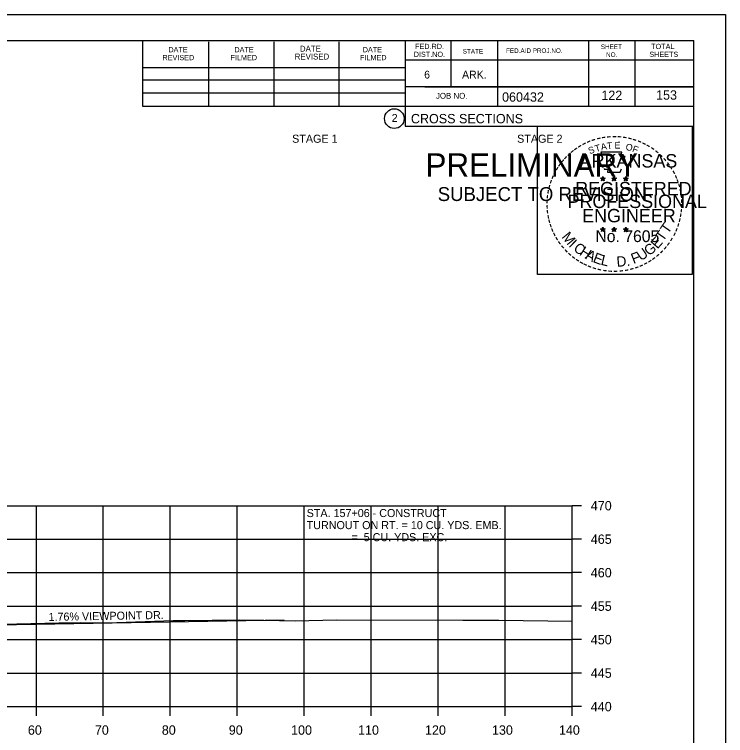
# Model space of a CAD drawing. Extents: x 1538688 to 1540766, y 656250 to 671912.
# Drawn here: x 1538914.9 to 1539021.1, y 666470.4 to 666578.1 of the extents above; entities that cross this region are included whole.
import ezdxf

# ---------------------------------------------------------------- set-up
doc = ezdxf.new("R2010")
doc.units = 0
for name, color, linetype in [('16', 7, 'Continuous'), ('18', 7, 'Continuous'), ('22', 7, 'Continuous'), ('26', 7, 'Continuous'), ('37', 7, 'Continuous'), ('7', 7, 'Continuous'), ('8', 7, 'Continuous'), ('9', 7, 'Continuous'), ('Borings', 7, 'Continuous'), ('Default', 7, 'Continuous'), ('Horizontal Alignment', 7, 'Continuous'), ('RipRap', 7, 'Continuous')]:
    doc.layers.add(name, color=color, linetype=linetype)

msp = doc.modelspace()

# ---------------------------------------------------------------- linework, layer by layer
at = {"layer": '18'}
msp.add_lwpolyline([(1538911.06, 666487.02), (1538921.53, 666487.26), (1538923.34, 666487.3), (1538924.76, 666487.31), (1538928.83, 666487.28), (1538938.6, 666487.62), (1538939.6, 666487.65), (1538940.37, 666487.65), (1538948.49, 666487.74), (1538951.25, 666487.66), (1538952.15, 666487.66), (1538956.85, 666487.6), (1538963.01, 666487.74), (1538981.87, 666487.66), (1538986.32, 666487.67), (1538987.26, 666487.66), (1538998.18, 666487.53)], dxfattribs=at)
at = {"layer": '22'}
for p, q in [((1538718.18, 666504.77), (1538998.18, 666504.77)), ((1538918.18, 666474.77), (1538918.18, 666504.77)), ((1538928.18, 666474.77), (1538928.18, 666504.77)), ((1538938.18, 666474.77), (1538938.18, 666504.77)), ((1538948.18, 666474.77), (1538948.18, 666504.77)), ((1538958.18, 666474.77), (1538958.18, 666504.77)), ((1538968.18, 666474.77), (1538968.18, 666504.77)), ((1538978.18, 666474.77), (1538978.18, 666504.77)), ((1538988.18, 666474.77), (1538988.18, 666504.77)), ((1538998.18, 666474.77), (1538998.18, 666504.77)), ((1538718.18, 666499.77), (1538998.18, 666499.77)), ((1538718.18, 666494.77), (1538998.18, 666494.77)), ((1538718.18, 666489.77), (1538998.18, 666489.77)), ((1538718.18, 666484.77), (1538998.18, 666484.77)), ((1538718.18, 666479.77), (1538998.18, 666479.77)), ((1538718.18, 666474.77), (1538998.18, 666474.77))]:
    msp.add_line(p, q, dxfattribs=at)
at = {"layer": '26'}
msp.add_line((1538687.78, 666578.12), (1539021.11, 666578.12), dxfattribs=at)
for points in [[(1538687.77, 666578.12), (1539021.11, 666578.12), (1539021.11, 666364.78), (1538687.77, 666364.78)], [(1538993.03, 666561.46), (1539016.13, 666561.46), (1539016.13, 666539.31), (1538993.03, 666539.31)]]:
    msp.add_lwpolyline(points, close=True, dxfattribs=at)
at = {"layer": '37'}
msp.add_line((1538955.18, 666487.7), (1538906.61, 666486.84), dxfattribs=at)
at = {"layer": '8'}
for p, q in [((1539002.44, 666553.67), (1539002.79, 666553.56)), ((1539002.44, 666553.67), (1539002.69, 666553.63)), ((1539002.44, 666553.67), (1539002.68, 666553.55)), ((1539002.57, 666553.26), (1539002.79, 666553.56)), ((1539002.57, 666553.26), (1539002.7, 666553.51)), ((1539002.57, 666553.26), (1539002.79, 666553.48)), ((1539002.79, 666553.93), (1539002.75, 666553.67)), ((1539002.79, 666553.56), (1539002.79, 666553.93)), ((1539002.79, 666553.93), (1539002.84, 666553.68)), ((1539003.13, 666553.67), (1539002.79, 666553.56)), ((1539003, 666553.26), (1539002.79, 666553.56)), ((1539003, 666553.26), (1539002.79, 666553.48)), ((1539003.13, 666553.67), (1539002.85, 666553.62)), ((1539003, 666553.26), (1539002.86, 666553.56)), ((1539003.13, 666553.67), (1539002.93, 666553.57)), ((1539004.11, 666553.67), (1539004.46, 666553.56)), ((1539004.11, 666553.67), (1539004.36, 666553.63)), ((1539004.11, 666553.67), (1539004.35, 666553.55)), ((1539004.24, 666553.26), (1539004.46, 666553.56)), ((1539004.24, 666553.26), (1539004.37, 666553.51)), ((1539004.24, 666553.26), (1539004.46, 666553.48)), ((1539004.46, 666553.93), (1539004.42, 666553.67)), ((1539004.46, 666553.56), (1539004.46, 666553.93)), ((1539004.46, 666553.93), (1539004.51, 666553.68)), ((1539004.8, 666553.67), (1539004.46, 666553.56)), ((1539004.67, 666553.26), (1539004.46, 666553.56)), ((1539004.67, 666553.26), (1539004.46, 666553.48)), ((1539004.8, 666553.67), (1539004.52, 666553.62)), ((1539004.67, 666553.26), (1539004.53, 666553.56)), ((1539004.8, 666553.67), (1539004.6, 666553.57)), ((1539005.87, 666553.66), (1539006.22, 666553.55)), ((1539005.87, 666553.66), (1539006.13, 666553.62)), ((1539005.87, 666553.66), (1539006.11, 666553.54)), ((1539006.01, 666553.25), (1539006.22, 666553.55)), ((1539006.01, 666553.25), (1539006.13, 666553.5)), ((1539006.01, 666553.25), (1539006.22, 666553.47)), ((1539006.22, 666553.91), (1539006.18, 666553.66)), ((1539006.22, 666553.55), (1539006.22, 666553.91)), ((1539006.22, 666553.91), (1539006.27, 666553.66)), ((1539006.57, 666553.66), (1539006.22, 666553.55)), ((1539006.43, 666553.25), (1539006.22, 666553.55)), ((1539006.43, 666553.25), (1539006.22, 666553.47)), ((1539006.57, 666553.66), (1539006.28, 666553.61)), ((1539006.43, 666553.25), (1539006.3, 666553.54)), ((1539006.57, 666553.66), (1539006.36, 666553.56)), ((1539002.43, 666546.1), (1539002.78, 666545.99)), ((1539002.43, 666546.1), (1539002.69, 666546.05)), ((1539002.43, 666546.1), (1539002.67, 666545.98)), ((1539002.57, 666545.69), (1539002.78, 666545.99)), ((1539002.57, 666545.69), (1539002.69, 666545.94)), ((1539002.57, 666545.69), (1539002.78, 666545.91)), ((1539002.78, 666546.35), (1539002.74, 666546.1)), ((1539002.78, 666545.99), (1539002.78, 666546.35)), ((1539002.78, 666546.35), (1539002.83, 666546.1)), ((1539003.13, 666546.1), (1539002.78, 666545.99)), ((1539003, 666545.69), (1539002.78, 666545.99)), ((1539003, 666545.69), (1539002.78, 666545.91)), ((1539003.13, 666546.1), (1539002.84, 666546.05)), ((1539003, 666545.69), (1539002.86, 666545.98)), ((1539003.13, 666546.1), (1539002.93, 666546)), ((1539004.1, 666546.1), (1539004.45, 666545.99)), ((1539004.1, 666546.1), (1539004.36, 666546.05)), ((1539004.1, 666546.1), (1539004.34, 666545.98)), ((1539004.24, 666545.69), (1539004.45, 666545.99)), ((1539004.24, 666545.69), (1539004.36, 666545.94)), ((1539004.24, 666545.69), (1539004.45, 666545.91)), ((1539004.45, 666546.35), (1539004.41, 666546.1)), ((1539004.45, 666545.99), (1539004.45, 666546.35)), ((1539004.45, 666546.35), (1539004.5, 666546.1)), ((1539004.8, 666546.1), (1539004.45, 666545.99)), ((1539004.67, 666545.69), (1539004.45, 666545.99)), ((1539004.67, 666545.69), (1539004.45, 666545.91)), ((1539004.8, 666546.1), (1539004.51, 666546.05)), ((1539004.67, 666545.69), (1539004.53, 666545.98)), ((1539004.8, 666546.1), (1539004.6, 666546)), ((1539005.87, 666546.09), (1539006.22, 666545.98)), ((1539005.87, 666546.09), (1539006.12, 666546.04)), ((1539005.87, 666546.09), (1539006.11, 666545.97)), ((1539006, 666545.68), (1539006.22, 666545.98)), ((1539006, 666545.68), (1539006.13, 666545.93)), ((1539006, 666545.68), (1539006.22, 666545.9)), ((1539006.22, 666546.34), (1539006.18, 666546.09)), ((1539006.22, 666545.98), (1539006.22, 666546.34)), ((1539006.22, 666546.34), (1539006.27, 666546.09)), ((1539006.57, 666546.09), (1539006.22, 666545.98)), ((1539006.43, 666545.68), (1539006.22, 666545.98)), ((1539006.43, 666545.68), (1539006.22, 666545.9)), ((1539006.57, 666546.09), (1539006.28, 666546.04)), ((1539006.43, 666545.68), (1539006.3, 666545.97)), ((1539006.57, 666546.09), (1539006.36, 666545.99))]:
    msp.add_line(p, q, dxfattribs=at)
for points in [[(1539002.48, 666557.55), (1539002.75, 666556.72)], [(1539005.99, 666556.63), (1539006.13, 666556.91), (1539005.45, 666556.89), (1539005.6, 666557.55), (1539002.48, 666557.55)], [(1539002.97, 666555.13), (1539002.97, 666555.04), (1539003.53, 666555.02), (1539003.48, 666554.55), (1539005.35, 666554.55), (1539005.55, 666555.08)], [(1539002.79, 666553.93), (1539003, 666553.26), (1539002.44, 666553.67), (1539003.13, 666553.67), (1539002.57, 666553.26), (1539002.79, 666553.93)], [(1539004.46, 666553.93), (1539004.67, 666553.26), (1539004.11, 666553.67), (1539004.8, 666553.67), (1539004.24, 666553.26), (1539004.46, 666553.93)], [(1539006.22, 666553.91), (1539006.43, 666553.25), (1539005.87, 666553.66), (1539006.57, 666553.66), (1539006.01, 666553.25), (1539006.22, 666553.91)], [(1539002.78, 666546.35), (1539003, 666545.69), (1539002.43, 666546.1), (1539003.13, 666546.1), (1539002.57, 666545.69), (1539002.78, 666546.35)], [(1539004.45, 666546.35), (1539004.67, 666545.69), (1539004.1, 666546.1), (1539004.8, 666546.1), (1539004.24, 666545.69), (1539004.45, 666546.35)], [(1539006.22, 666546.34), (1539006.43, 666545.68), (1539005.87, 666546.09), (1539006.57, 666546.09), (1539006, 666545.68), (1539006.22, 666546.34)]]:
    msp.add_lwpolyline(points, dxfattribs=at)
for centre, radius in [((1539002.79, 666553.56), 0.172), ((1539002.79, 666553.56), 0.145), ((1539002.79, 666553.56), 0.116), ((1539002.79, 666553.56), 0.0991), ((1539002.79, 666553.56), 0.0747), ((1539002.79, 666553.56), 0.0495), ((1539002.79, 666553.56), 0.0296), ((1539004.46, 666553.56), 0.172), ((1539004.46, 666553.56), 0.145), ((1539004.46, 666553.56), 0.116), ((1539004.46, 666553.56), 0.0991), ((1539004.46, 666553.56), 0.0747), ((1539004.46, 666553.56), 0.0495), ((1539004.46, 666553.56), 0.0296), ((1539006.22, 666553.55), 0.172), ((1539006.22, 666553.55), 0.145), ((1539006.22, 666553.55), 0.116), ((1539006.22, 666553.55), 0.0991), ((1539006.22, 666553.55), 0.0747), ((1539006.22, 666553.55), 0.0495), ((1539006.22, 666553.55), 0.0296), ((1539002.78, 666545.99), 0.172), ((1539002.78, 666545.99), 0.145), ((1539002.78, 666545.99), 0.116), ((1539002.78, 666545.99), 0.0991), ((1539002.78, 666545.99), 0.0747), ((1539002.78, 666545.99), 0.0495), ((1539002.78, 666545.99), 0.0296), ((1539004.45, 666545.99), 0.172), ((1539004.45, 666545.99), 0.145), ((1539004.45, 666545.99), 0.116), ((1539004.45, 666545.99), 0.0991), ((1539004.45, 666545.99), 0.0747), ((1539004.45, 666545.99), 0.0495), ((1539004.45, 666545.99), 0.0296), ((1539006.22, 666545.98), 0.172), ((1539006.22, 666545.98), 0.145), ((1539006.22, 666545.98), 0.116), ((1539006.22, 666545.98), 0.0991), ((1539006.22, 666545.98), 0.0747), ((1539006.22, 666545.98), 0.0495), ((1539006.22, 666545.98), 0.0296)]:
    msp.add_circle(centre, radius, dxfattribs=at)
at = {"layer": 'Borings'}
for p, q in [((1538998.18, 666474.77), (1538998.18, 666504.77)), ((1538999.58, 666504.77), (1538998.18, 666504.77)), ((1538999.58, 666499.77), (1538998.18, 666499.77)), ((1538999.58, 666494.77), (1538998.18, 666494.77)), ((1538999.58, 666489.77), (1538998.18, 666489.77)), ((1538999.58, 666484.77), (1538998.18, 666484.77)), ((1538999.58, 666479.77), (1538998.18, 666479.77)), ((1538718.18, 666474.77), (1538998.18, 666474.77)), ((1538918.18, 666473.37), (1538918.18, 666474.77)), ((1538928.18, 666473.37), (1538928.18, 666474.77)), ((1538938.18, 666473.37), (1538938.18, 666474.77)), ((1538948.18, 666473.37), (1538948.18, 666474.77)), ((1538958.18, 666473.37), (1538958.18, 666474.77)), ((1538968.18, 666473.37), (1538968.18, 666474.77)), ((1538978.18, 666473.37), (1538978.18, 666474.77)), ((1538988.18, 666473.37), (1538988.18, 666474.77)), ((1538998.18, 666473.37), (1538998.18, 666474.77)), ((1538999.58, 666474.77), (1538998.18, 666474.77))]:
    msp.add_line(p, q, dxfattribs=at)
at = {"layer": 'RipRap'}
for p, q in [((1538700.18, 666574.23), (1539016.36, 666574.23)), ((1538934.1, 666564.35), (1538934.1, 666574.23)), ((1538943.96, 666564.35), (1538943.96, 666574.03)), ((1538953.72, 666564.35), (1538953.72, 666574.03)), ((1538963.4, 666564.35), (1538963.4, 666574.03)), ((1538973.26, 666574.23), (1538973.26, 666561.43)), ((1538980.1, 666574.23), (1538980.1, 666567.29)), ((1538987.04, 666574.23), (1538987.04, 666564.35)), ((1539000.62, 666574.23), (1539000.62, 666564.35)), ((1539007.56, 666574.23), (1539007.56, 666564.35)), ((1539016.36, 666368.77), (1539016.36, 666574.23)), ((1539016.36, 666571.29), (1538973.26, 666571.29)), ((1539016.36, 666571.31), (1539016.36, 666571.31)), ((1538934.1, 666570.21), (1538973.26, 666570.21)), ((1538934.1, 666568.35), (1538973.26, 666568.35)), ((1539016.36, 666567.29), (1538973.26, 666567.29)), ((1538976.22, 666567.29), (1539016.36, 666567.29)), ((1538934.1, 666564.35), (1538934.1, 666566.41)), ((1538934.1, 666566.41), (1538973.26, 666566.41)), ((1539016.36, 666564.35), (1538934.1, 666564.35)), ((1538973.26, 666561.43), (1539016.36, 666561.43))]:
    msp.add_line(p, q, dxfattribs=at)
msp.add_circle((1538971.64, 666562.56), 1.47, dxfattribs=at)

# ---------------------------------------------------------------- texts
at = {"layer": '16'}
msp.add_text('1.76% VIEWPOINT DR.', height=1.2, rotation=1.0076, dxfattribs=at).set_placement((1538920.01, 666487.56))
at = {"layer": '7'}
for s, height, p in [('122', 1.4, (1539002.56, 666565.34)), ('153', 1.4, (1539010.73, 666565.39)), ('STA. 157+06 - CONSTRUCT', 1.2, (1538958.55, 666503.07)), ('TURNOUT ON RT. = 10 CU. YDS. EMB.', 1.2, (1538958.55, 666501.27)), ('               =  5 CU. YDS. EXC.', 1.2, (1538958.55, 666499.47))]:
    msp.add_text(s, height=height, dxfattribs=at).set_placement(p)
at = {"layer": '8'}
for s, height, rotation, p in [('-', 1.6, 19.1761, (1539001.23, 666558.68)), ('-', 1.6, 13.6301, (1539001.98, 666558.92)), ('-', 1.6, 10.2193, (1539002.66, 666559.08)), ('-', 1.6, 5.8968, (1539003.38, 666559.19)), ('-', 1.6, 0.1862, (1539004.16, 666559.26)), ('-', 1.6, 357.743, (1539004.88, 666559.25)), ('-', 1.6, 352.1617, (1539005.62, 666559.19)), ('-', 1.6, 347.2049, (1539006.34, 666559.08)), ('-', 1.6, 342.3362, (1539006.98, 666558.92)), ('-', 1.6, 34.0636, (1538999.36, 666557.72)), ('-', 1.6, 28.7918, (1538999.96, 666558.09)), ('-', 1.6, 24.3072, (1539000.59, 666558.41)), ('T', 1, 16.4036, (1539001.75, 666557.56)), ('A', 1, 11.2132, (1539002.57, 666557.81)), ('T', 1, 6.0228, (1539003.42, 666557.98)), ('E', 1, 0.8323, (1539004.53, 666558.09)), ('O', 1, 350.4515, (1539006.13, 666557.88)), ('F', 1, 340.0707, (1539007.09, 666557.65)), ('-', 1.6, 337.8551, (1539007.71, 666558.7)), ('-', 1.6, 334.1211, (1539008.34, 666558.43)), ('-', 1.6, 329.6409, (1539008.92, 666558.15)), ('-', 1.6, 42.9622, (1538997.88, 666556.53)), ('-', 1.6, 38.9507, (1538998.31, 666556.95)), ('-', 1.6, 36.2317, (1538998.79, 666557.33)), ('S', 1, 21.594, (1539000.83, 666557.23)), ('-', 1.6, 325.8627, (1539009.57, 666557.79)), ('-', 1.6, 320.5297, (1539010.18, 666557.36)), ('-', 1.6, 50.6142, (1538997.03, 666555.57)), ('-', 1.6, 48.423, (1538997.43, 666556.05)), ('ARKANSAS', 2, 360, (1538999.33, 666555.26)), ('-', 1.6, 315.5786, (1539010.77, 666556.87)), ('-', 1.6, 309.8797, (1539011.34, 666556.32)), ('-', 1.6, 58.0706, (1538996.29, 666554.47)), ('-', 1.6, 54.2325, (1538996.61, 666555)), ('-', 1.6, 306.6522, (1539011.87, 666555.72)), ('-', 1.4, 303.6753, (1539012.35, 666555.15)), ('-', 1.6, 62.8713, (1538995.97, 666553.86)), ('-', 1.6, 299.6684, (1539012.67, 666554.55)), ('-', 1.6, 294.6628, (1539013, 666553.93)), ('-', 1.6, 72.3945, (1538995.5, 666552.62)), ('-', 1.6, 67.7743, (1538995.72, 666553.25)), ('REGISTERED', 2, 360, (1538998.65, 666551.11)), ('DWB', 0.01, 360, (1539002.77, 666553.56)), ('DWB', 0.01, 360, (1539004.44, 666553.56)), ('DWB', 0.01, 360, (1539006.21, 666553.54)), ('-', 1.6, 290.5728, (1539013.25, 666553.36)), ('-', 1.6, 75.461, (1538995.3, 666551.9)), ('-', 1.6, 285.1233, (1539013.49, 666552.78)), ('-', 1.6, 280.5493, (1539013.69, 666552.03)), ('-', 1.6, 85.1863, (1538995.09, 666550.5)), ('-', 1.6, 81.2013, (1538995.17, 666551.19)), ('PROFESSIONAL', 2, 360, (1538997.51, 666549.21)), ('-', 1.6, 276.5962, (1539013.85, 666551.27)), ('-', 1.6, 89.0622, (1538995.07, 666549.8)), ('-', 1.6, 274.3301, (1539013.91, 666550.54)), ('-', 1.6, 269.9407, (1539013.94, 666549.91)), ('-', 1.6, 94.1959, (1538995.1, 666549.07)), ('-', 1.6, 98.9479, (1538995.17, 666548.41)), ('ENGINEER', 2, 360, (1538999.69, 666547.08)), ('-', 1.6, 263.5172, (1539013.93, 666549.25)), ('-', 1.6, 101.7149, (1538995.31, 666547.67)), ('-', 1.6, 255.7626, (1539013.74, 666547.91)), ('-', 1.6, 260.9953, (1539013.85, 666548.59)), ('-', 1.6, 105.4578, (1538995.47, 666547.08)), ('-', 1.6, 109.0874, (1538995.69, 666546.45)), ('T', 1.54, 55.055, (1539012.5, 666545.25)), ('-', 1.6, 252.8681, (1539013.56, 666547.19)), ('-', 1.6, 114.0643, (1538995.94, 666545.85)), ('-', 1.6, 115.7289, (1538996.24, 666545.23)), ('M', 1.54, 308.9175, (1538996.55, 666544.88)), ('No. 7605', 1.757, 360, (1539001.67, 666544.13)), ('DWB', 0.01, 360, (1539002.77, 666545.98)), ('DWB', 0.01, 360, (1539004.44, 666545.98)), ('DWB', 0.01, 360, (1539006.2, 666545.97)), ('T', 1.54, 55.055, (1539011.77, 666544.13)), ('-', 1.6, 244.6197, (1539013.08, 666545.89)), ('-', 1.6, 247.8887, (1539013.34, 666546.52)), ('-', 1.6, 120.4471, (1538996.6, 666544.65)), ('I', 1.54, 316.4636, (1538997.6, 666543.56)), ('E', 1.54, 48.7313, (1539010.93, 666543.01)), ('-', 1.6, 239.0712, (1539012.68, 666545.14)), ('-', 1.6, 125.8934, (1538997, 666544.09)), ('-', 1.6, 130.7181, (1538997.47, 666543.54)), ('C', 1.54, 324.0197, (1538998.27, 666542.94)), ('H', 1.54, 327.5342, (1538999.18, 666542.28)), ('G', 1.54, 38.2173, (1539009.67, 666541.99)), ('-', 1.6, 231.2538, (1539011.85, 666543.92)), ('-', 1.6, 233.8452, (1539012.28, 666544.49)), ('-', 1.6, 134.2238, (1538997.98, 666542.99)), ('-', 1.6, 138.9338, (1538998.51, 666542.53)), ('A', 1.54, 332.5513, (1539000.03, 666541.74)), ('E', 1.54, 339.2068, (1539001.19, 666541.18)), ('F', 1.54, 20.8202, (1539007.34, 666540.86)), ('U', 1.54, 34.4052, (1539008.47, 666541.25)), ('-', 1.6, 221.0851, (1539010.85, 666542.85)), ('-', 1.6, 225.7653, (1539011.37, 666543.36)), ('-', 1.6, 144.6463, (1538999.06, 666542.12)), ('-', 1.6, 148.0898, (1538999.63, 666541.75)), ('-', 1.6, 151.5704, (1539000.2, 666541.42)), ('L', 1.54, 346.2929, (1539002.38, 666540.76)), ('D.', 1.54, 5.2602, (1539004.89, 666540.42)), ('-', 1.6, 212.2491, (1539009.77, 666541.99)), ('-', 1.6, 215.7363, (1539010.3, 666542.38)), ('-', 1.6, 154.6002, (1539000.73, 666541.18)), ('-', 1.6, 158.5612, (1539001.35, 666540.92)), ('-', 1.6, 162.7983, (1539002.04, 666540.71)), ('-', 1.6, 167.5555, (1539002.75, 666540.55)), ('-', 1.6, 195.4743, (1539007.29, 666540.81)), ('-', 1.6, 200.7184, (1539007.97, 666541.05)), ('-', 1.6, 204.2516, (1539008.59, 666541.32)), ('-', 1.6, 207.3568, (1539009.21, 666541.64)), ('-', 1.6, 173.1155, (1539003.52, 666540.44)), ('-', 1.6, 176.5183, (1539004.27, 666540.38)), ('-', 1.6, 181.5918, (1539005.02, 666540.4)), ('-', 1.6, 185.8167, (1539005.83, 666540.48)), ('-', 1.6, 191.2858, (1539006.56, 666540.61))]:
    msp.add_text(s, height=height, rotation=rotation, dxfattribs=at).set_placement(p)
at = {"layer": '9'}
for s, height, p in [('PRELIMINARY', 3.5, (1538976.31, 666553.89)), ('DWB', 0.01, (1538977.06, 666555.74)), ('SUBJECT TO REVISION', 2.0751, (1538978.12, 666550.26))]:
    msp.add_text(s, height=height, rotation=360, dxfattribs=at).set_placement(p)
at = {"layer": 'Default'}
for s, p in [('STAGE 1', (1538956.38, 666558.96)), ('STAGE 2', (1538989.98, 666558.96))]:
    msp.add_text(s, height=1.2, dxfattribs=at).set_placement(p)
at = {"layer": 'Horizontal Alignment'}
for s, p in [('470', (1539000.98, 666504.07)), ('465', (1539000.98, 666499.07)), ('460', (1539000.98, 666494.07)), ('455', (1539000.98, 666489.07)), ('450', (1539000.98, 666484.07)), ('445', (1539000.98, 666479.07)), ('440', (1539000.98, 666474.07)), ('60', (1538916.92, 666470.57)), ('70', (1538926.92, 666470.57)), ('80', (1538936.92, 666470.57)), ('90', (1538946.92, 666470.57)), ('100', (1538956.22, 666470.57)), ('110', (1538966.22, 666470.57)), ('120', (1538976.22, 666470.57)), ('130', (1538986.22, 666470.57)), ('140', (1538996.22, 666470.57))]:
    msp.add_text(s, height=1.4, dxfattribs=at).set_placement(p)
at = {"layer": 'RipRap'}
for s, height, p in [('FED.RD.', 0.782, (1538974.74, 666572.95)), ('SHEET', 0.684, (1539002.48, 666572.95)), ('TOTAL', 0.782, (1539010, 666572.95)), ('DATE', 0.782, (1538937.9, 666572.47)), ('DATE', 0.782, (1538947.76, 666572.47)), ('DATE', 0.879, (1538957.54, 666572.57)), ('DATE', 0.782, (1538966.92, 666572.47)), ('DIST.NO.', 0.782, (1538974.54, 666571.77)), ('STATE', 0.684, (1538981.86, 666572.27)), ('FED.AID PROJ.NO.', 0.684, (1538988.32, 666572.37)), ('NO.', 0.684, (1539003.26, 666571.77)), ('SHEETS', 0.782, (1539009.72, 666571.77)), ('REVISED', 0.782, (1538937.02, 666571.29)), ('FILMED', 0.782, (1538947.18, 666571.29)), ('REVISED', 0.879, (1538956.76, 666571.39)), ('FILMED', 0.782, (1538966.52, 666571.29)), ('6', 1.17, (1538976.1, 666568.55)), ('ARK.', 1.172, (1538981.76, 666568.55)), ('JOB NO.', 0.879, (1538977.86, 666565.53)), ('060432', 1.4, (1538987.73, 666565.09)), ('2', 1.17, (1538971.26, 666562.08)), ('CROSS SECTIONS', 1.4, (1538974.12, 666561.86))]:
    msp.add_text(s, height=height, rotation=360, dxfattribs=at).set_placement(p)

doc.saveas('drawing.dxf')
